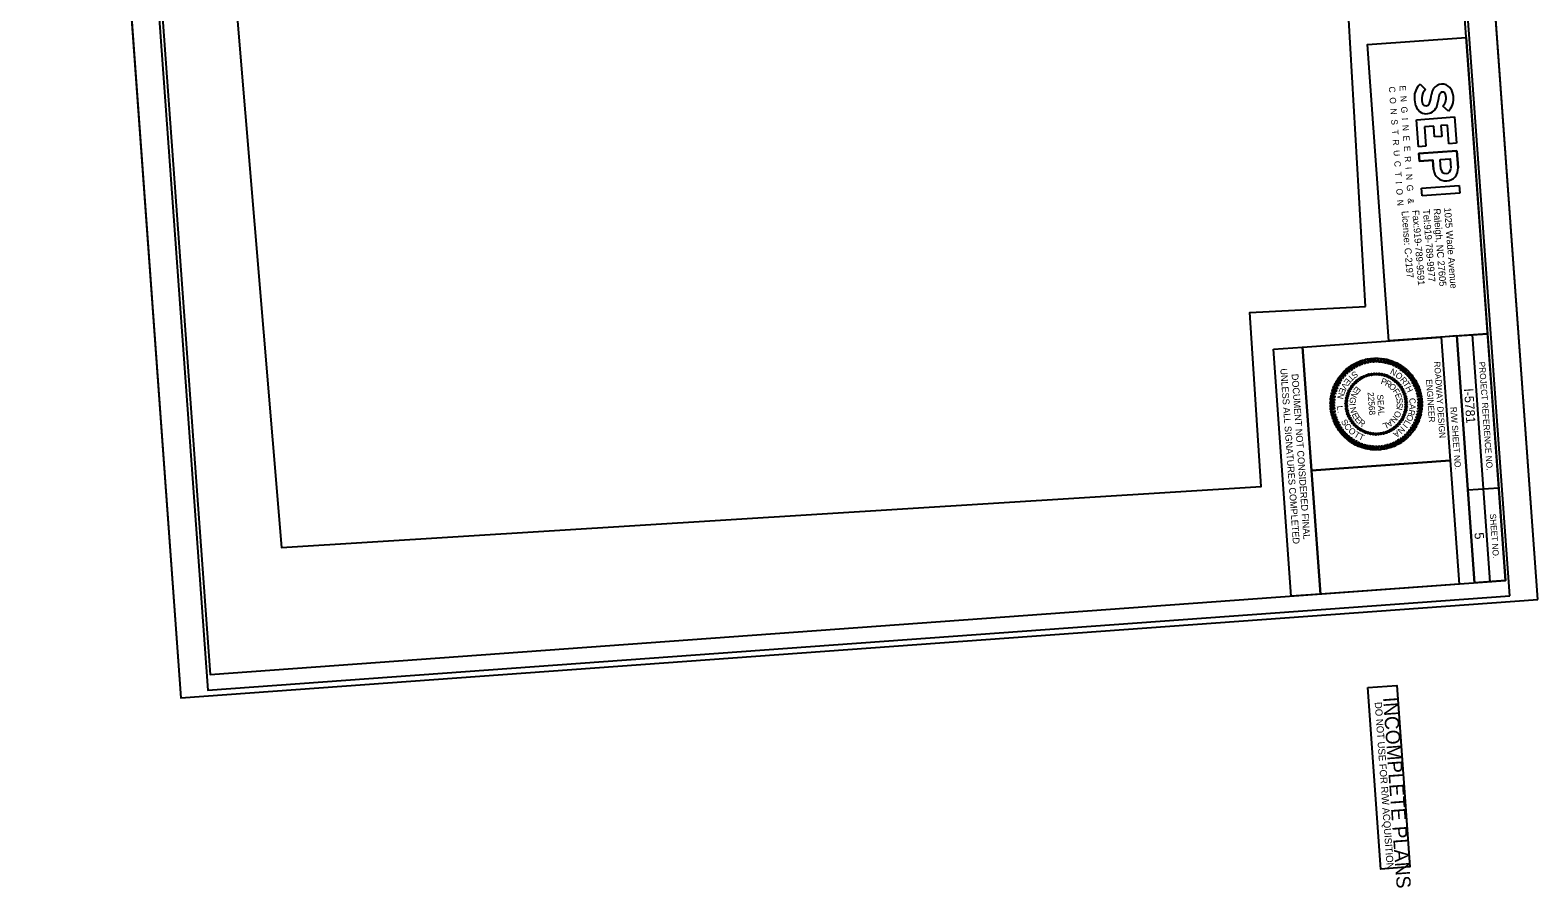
# Model space of a CAD drawing. Extents: x 2130580 to 2132747, y 641711 to 644338.
# Drawn here: x 2131528 to 2132747, y 641711 to 642404 of the extents above; entities that cross this region are included whole.
import ezdxf

# ---------------------------------------------------------------- set-up
doc = ezdxf.new("R2010")
doc.units = 0
for name, color, linetype in [('Old_Level_2', 7, 'Continuous'), ('Old_Level_58', 7, 'Continuous'), ('Old_Level_61', 7, 'Continuous'), ('Raster_Level_1', 7, 'Continuous'), ('Sheet Border Standard 30in CELL', 7, 'Continuous'), ('Sheet Cutting Line CELL', 7, 'Continuous'), ('Sheet Data Field CELL', 7, 'Continuous'), ('Sheet PE Seal Cell', 7, 'Continuous'), ('Sheet Plot Border Inside CELL', 7, 'Continuous'), ('Sheet Plot Border Outside CELL', 7, 'Continuous'), ('Sheet Sticker Exception Certification CELL', 7, 'Continuous'), ('Sheet Sticker Incomplete CELL', 7, 'Continuous')]:
    doc.layers.add(name, color=color, linetype=linetype)

msp = doc.modelspace()

# ---------------------------------------------------------------- linework, layer by layer
at = {"layer": 'Old_Level_58'}
msp.add_lwpolyline([(2132688.9, 642398), (2132706.3, 642158.6), (2132626.5, 642152.8), (2132609.1, 642392.3)], close=True, dxfattribs=at)
at = {"layer": 'Old_Level_61'}
for p, q in [((2132651.8, 642360.1), (2132656.1, 642355.9)), ((2132674.8, 642338.3), (2132670.1, 642342.4)), ((2132648.8, 642331.5), (2132679.4, 642333.7)), ((2132650.4, 642309.5), (2132648.8, 642331.5)), ((2132662.7, 642326.3), (2132655.2, 642325.8)), ((2132663.3, 642317.6), (2132662.7, 642326.3)), ((2132673.9, 642327.1), (2132668.6, 642326.8)), ((2132668.6, 642326.8), (2132669.2, 642318)), ((2132675, 642312), (2132673.9, 642327.1)), ((2132679.4, 642333.7), (2132681, 642312.4)), ((2132655.2, 642325.8), (2132656.4, 642310)), ((2132669.2, 642318), (2132663.3, 642317.6)), ((2132656.4, 642310), (2132650.4, 642309.5)), ((2132681, 642312.4), (2132675, 642312)), ((2132682.4, 642292.6), (2132681.4, 642306.4)), ((2132668.6, 642291.6), (2132668, 642299.2)), ((2132652.9, 642276.1), (2132683.4, 642278.4)), ((2132683.4, 642278.4), (2132683.9, 642272.2)), ((2132653.3, 642270), (2132652.9, 642276.1)), ((2132683.9, 642272.2), (2132653.3, 642270))]:
    msp.add_line(p, q, dxfattribs=at)
for points in [[(2132662.6, 642291.2), (2132662.1, 642298.8), (2132651.3, 642298), (2132650.8, 642304.2), (2132681.4, 642306.4)], [(2132681.4, 642306.4), (2132650.8, 642304.2), (2132651.3, 642298), (2132662.1, 642298.8), (2132662.6, 642291.2)], [(2132681.4, 642306.4), (2132682.4, 642292.6)], [(2132668, 642299.2), (2132675.9, 642299.8), (2132676.5, 642292.2)], [(2132668, 642299.2), (2132675.9, 642299.8), (2132676.5, 642292.2)], [(2132668.6, 642291.6), (2132668, 642299.2)]]:
    msp.add_lwpolyline(points, dxfattribs=at)
for centre, radius, start, end in [((2132660.5, 642349.9), 13.4, 130.5125, 183.1662), ((2132662.7, 642349), 9.54, 133.3574, 179.9159), ((2132623.6, 642356.4), 37.6, 341.9287, 353.2035), ((2132673.2, 642350.1), 12.5, 148.1705, 171.4938), ((2132669.5, 642351.7), 8.51, 41.8801, 143.8084), ((2132624.9, 642355.6), 42.5, 341.3478, 353.5291), ((2132671.9, 642350.1), 4.86, 138.9767, 170.9918), ((2132669.8, 642351.3), 2.54, 17.6741, 129.6578), ((2132663.4, 642349), 9.35, 315.7637, 19.3408), ((2132664.1, 642348.5), 14.7, 316.2757, 37.1211), ((2132667.4, 642348.9), 20.3, 179.2769, 197.9175), ((2132656.8, 642345.4), 9.06, 198.0418, 337.7347), ((2132665, 642348.6), 11.9, 177.9903, 199.1916), ((2132656.5, 642345.7), 2.95, 200.2565, 340.7914), ((2132672.5, 642291.9), 9.91, 184.1516, 4.1516), ((2132672.5, 642291.9), 9.91, 184.1516, 4.1516), ((2132672.5, 642291.9), 3.95, 184.1516, 4.1516), ((2132672.5, 642291.9), 3.95, 184.1516, 4.1516)]:
    msp.add_arc(centre, radius, start, end, dxfattribs=at)
at = {"layer": 'Raster_Level_1'}
msp.add_lwpolyline([(2132607.7, 642180.7), (2132538.9, 643362), (2131621.6, 643297.4), (2131731.3, 641985.8), (2132523.3, 642035.1), (2132514, 642175.6)], close=True, dxfattribs=at)
at = {"layer": 'Sheet Border Standard 30in CELL'}
for p, q in [((2132681.3, 642156.8), (2132668.8, 642155.9)), ((2132681.3, 642156.8), (2132695.7, 641957.3)), ((2132681.3, 642156.8), (2132695.7, 641957.3)), ((2132693.8, 642157.7), (2132708.2, 641958.2)), ((2132676.1, 642056.1), (2132563.9, 642048)), ((2132715.3, 642033.9), (2132690.3, 642032.1))]:
    msp.add_line(p, q, dxfattribs=at)
for points in [[(2132720.7, 641959.1), (2132612.4, 643455.2), (2131565.1, 643379.3), (2131673.5, 641883.2)], [(2132668.8, 642155.9), (2132676.1, 642056.1), (2132563.8, 642048), (2132556.6, 642147.8)], [(2132706.3, 642158.6), (2132720.7, 641959.1), (2132695.7, 641957.3), (2132681.3, 642156.8)], [(2132676.1, 642056.1), (2132683.3, 641956.4), (2132571.1, 641948.2), (2132563.8, 642048)]]:
    msp.add_lwpolyline(points, close=True, dxfattribs=at)
at = {"layer": 'Sheet Cutting Line CELL'}
for p, q in [((2132746.9, 641943.9), (2132625.2, 643623.5)), ((2131528.1, 643544.1), (2131649.8, 641864.5))]:
    msp.add_line(p, q, dxfattribs=at)
at = {"layer": 'Sheet PE Seal Cell'}
for points in [[(2132595.7, 642128.9), (2132593.7, 642131.3), (2132595, 642132.2), (2132596.7, 642129.6)], [(2132597.7, 642130.3), (2132595.8, 642132.8), (2132597.2, 642133.6), (2132598.6, 642130.9)], [(2132599.7, 642131.5), (2132598, 642134.1), (2132599.5, 642134.9), (2132600.7, 642132)], [(2132601.8, 642132.6), (2132600.3, 642135.3), (2132601.8, 642135.9), (2132602.9, 642133)], [(2132604, 642133.5), (2132602.7, 642136.3), (2132604.2, 642136.9), (2132605.1, 642133.9)], [(2132606.2, 642134.3), (2132605.2, 642137.2), (2132606.7, 642137.6), (2132607.3, 642134.6)], [(2132608.5, 642134.9), (2132607.6, 642137.9), (2132609.2, 642138.2), (2132609.7, 642135.1)], [(2132610.9, 642135.4), (2132610.2, 642138.4), (2132611.8, 642138.6), (2132612, 642135.5)], [(2132613.2, 642135.6), (2132612.8, 642138.7), (2132614.4, 642138.8), (2132614.4, 642135.7)], [(2132615.6, 642135.8), (2132615.3, 642138.9), (2132617, 642138.9), (2132616.7, 642135.8)], [(2132618, 642135.7), (2132617.9, 642138.9), (2132619.5, 642138.7), (2132619.1, 642135.7)], [(2132620.3, 642135.5), (2132620.5, 642138.7), (2132622.1, 642138.4), (2132621.5, 642135.4)], [(2132622.7, 642135.2), (2132623.1, 642138.3), (2132624.7, 642137.9), (2132623.8, 642134.9)], [(2132625, 642134.6), (2132625.6, 642137.7), (2132627.1, 642137.2), (2132626.1, 642134.3)], [(2132627.2, 642134), (2132628.1, 642137), (2132629.6, 642136.4), (2132628.3, 642133.6)], [(2132629.5, 642133.1), (2132630.5, 642136), (2132632, 642135.4), (2132630.5, 642132.6)], [(2132631.6, 642132.1), (2132632.9, 642135), (2132634.3, 642134.2), (2132632.6, 642131.6)], [(2132633.7, 642131), (2132635.1, 642133.7), (2132636.5, 642132.8), (2132634.7, 642130.4)], [(2132635.7, 642129.7), (2132637.3, 642132.3), (2132638.6, 642131.4), (2132636.6, 642129)], [(2132586.5, 642118.2), (2132583.7, 642119.6), (2132584.5, 642120.9), (2132587, 642119.2)], [(2132587.7, 642120.3), (2132585, 642121.8), (2132585.9, 642123.1), (2132588.3, 642121.2)], [(2132589.1, 642122.2), (2132586.5, 642123.9), (2132587.5, 642125.2), (2132589.8, 642123.1)], [(2132590.5, 642124), (2132588.1, 642125.9), (2132589.2, 642127.1), (2132591.3, 642124.9)], [(2132592.2, 642125.8), (2132589.8, 642127.9), (2132591, 642129), (2132593, 642126.6)], [(2132593.9, 642127.4), (2132591.7, 642129.6), (2132593, 642130.7), (2132594.8, 642128.1)], [(2132637.6, 642128.2), (2132639.4, 642130.8), (2132640.6, 642129.7), (2132638.5, 642127.5)], [(2132639.4, 642126.7), (2132641.4, 642129.1), (2132642.5, 642128), (2132640.2, 642125.9)], [(2132641.1, 642125), (2132643.2, 642127.3), (2132644.3, 642126.1), (2132641.8, 642124.2)], [(2132642.6, 642123.2), (2132644.9, 642125.3), (2132645.9, 642124.1), (2132643.3, 642122.3)], [(2132644, 642121.3), (2132646.5, 642123.3), (2132647.4, 642121.9), (2132644.7, 642120.4)], [(2132645.3, 642119.4), (2132647.9, 642121.1), (2132648.7, 642119.7), (2132645.9, 642118.4)], [(2132646.5, 642117.3), (2132649.2, 642118.9), (2132649.9, 642117.4), (2132647, 642116.3)], [(2132582.7, 642107), (2132579.6, 642107.3), (2132579.9, 642108.9), (2132582.8, 642108.2)], [(2132583.1, 642109.4), (2132580, 642109.9), (2132580.4, 642111.5), (2132583.4, 642110.5)], [(2132583.7, 642111.7), (2132580.7, 642112.4), (2132581.2, 642113.9), (2132584.1, 642112.8)], [(2132584.5, 642113.9), (2132581.5, 642114.9), (2132582.1, 642116.3), (2132584.9, 642115)], [(2132585.4, 642116.1), (2132582.5, 642117.2), (2132583.2, 642118.7), (2132585.9, 642117.1)], [(2132647.5, 642115.1), (2132650.3, 642116.5), (2132650.9, 642115), (2132647.9, 642114.1)], [(2132648.4, 642112.9), (2132651.2, 642114.1), (2132651.7, 642112.6), (2132648.7, 642111.8)], [(2132649.1, 642110.6), (2132652, 642111.6), (2132652.4, 642110.1), (2132649.3, 642109.5)], [(2132649.6, 642108.3), (2132652.6, 642109.1), (2132652.9, 642107.5), (2132649.8, 642107.2)], [(2132582.3, 642102.3), (2132579.1, 642102.2), (2132579.2, 642103.8), (2132582.3, 642103.5)], [(2132582.3, 642100), (2132579.2, 642099.6), (2132579.2, 642101.2), (2132582.3, 642101.1)], [(2132582.4, 642104.7), (2132579.3, 642104.8), (2132579.4, 642106.4), (2132582.5, 642105.8)], [(2132582.5, 642097.6), (2132579.4, 642097), (2132579.3, 642098.6), (2132582.4, 642098.7)], [(2132582.9, 642095.2), (2132579.9, 642094.5), (2132579.6, 642096.1), (2132582.7, 642096.4)], [(2132649.8, 642096.5), (2132652.9, 642096.2), (2132652.6, 642094.6), (2132649.6, 642095.4)], [(2132650, 642106), (2132653, 642106.6), (2132653.2, 642105), (2132650.1, 642104.9)], [(2132650.1, 642098.9), (2132653.2, 642098.8), (2132653, 642097.2), (2132650, 642097.8)], [(2132650.2, 642103.6), (2132653.3, 642104), (2132653.3, 642102.4), (2132650.2, 642102.5)], [(2132650.2, 642101.3), (2132653.3, 642101.4), (2132653.3, 642099.8), (2132650.2, 642100.1)], [(2132583.4, 642092.9), (2132580.5, 642091.9), (2132580.1, 642093.5), (2132583.1, 642094)], [(2132584.1, 642090.7), (2132581.2, 642089.5), (2132580.8, 642091), (2132583.8, 642091.8)], [(2132585, 642088.5), (2132582.2, 642087.1), (2132581.6, 642088.6), (2132584.5, 642089.5)], [(2132586, 642086.3), (2132583.3, 642084.7), (2132582.6, 642086.2), (2132585.5, 642087.3)], [(2132587.1, 642084.2), (2132584.6, 642082.5), (2132583.8, 642083.9), (2132586.6, 642085.2)], [(2132588.4, 642082.2), (2132586, 642080.3), (2132585.1, 642081.7), (2132587.8, 642083.2)], [(2132644.8, 642083.3), (2132647.5, 642081.8), (2132646.6, 642080.5), (2132644.2, 642082.4)], [(2132646, 642085.4), (2132648.8, 642084), (2132648, 642082.6), (2132645.4, 642084.4)], [(2132647.1, 642087.5), (2132650, 642086.3), (2132649.2, 642084.9), (2132646.6, 642086.5)], [(2132648, 642089.7), (2132651, 642088.7), (2132650.3, 642087.2), (2132647.6, 642088.6)], [(2132648.8, 642091.9), (2132651.8, 642091.2), (2132651.3, 642089.7), (2132648.4, 642090.8)], [(2132649.4, 642094.2), (2132652.5, 642093.7), (2132652, 642092.1), (2132649.1, 642093.1)], [(2132589.9, 642080.4), (2132587.6, 642078.2), (2132586.6, 642079.5), (2132589.2, 642081.2)], [(2132591.4, 642078.6), (2132589.3, 642076.3), (2132588.2, 642077.5), (2132590.7, 642079.4)], [(2132593.1, 642076.9), (2132591.1, 642074.5), (2132590, 642075.6), (2132592.3, 642077.7)], [(2132594.9, 642075.3), (2132593.1, 642072.8), (2132591.9, 642073.9), (2132594, 642076.1)], [(2132596.8, 642073.9), (2132595.2, 642071.3), (2132593.9, 642072.2), (2132595.9, 642074.6)], [(2132598.8, 642072.6), (2132597.3, 642069.9), (2132596, 642070.7), (2132597.8, 642073.2)], [(2132600.9, 642071.5), (2132599.6, 642068.6), (2132598.2, 642069.4), (2132599.9, 642072)], [(2132603, 642070.5), (2132602, 642067.5), (2132600.5, 642068.2), (2132602, 642070.9)], [(2132628.5, 642070.1), (2132629.8, 642067.2), (2132628.2, 642066.7), (2132627.4, 642069.7)], [(2132630.7, 642071), (2132632.2, 642068.3), (2132630.7, 642067.6), (2132629.6, 642070.5)], [(2132632.8, 642072.1), (2132634.5, 642069.5), (2132633, 642068.7), (2132631.8, 642071.5)], [(2132634.8, 642073.3), (2132636.7, 642070.8), (2132635.3, 642070), (2132633.8, 642072.7)], [(2132636.7, 642074.7), (2132638.8, 642072.3), (2132637.5, 642071.4), (2132635.8, 642074)], [(2132638.6, 642076.2), (2132640.8, 642074), (2132639.5, 642072.9), (2132637.7, 642075.4)], [(2132640.3, 642077.8), (2132642.7, 642075.7), (2132641.5, 642074.6), (2132639.5, 642077)], [(2132641.9, 642079.5), (2132644.4, 642077.6), (2132643.3, 642076.5), (2132641.2, 642078.7)], [(2132643.4, 642081.4), (2132646, 642079.7), (2132645, 642078.4), (2132642.7, 642080.5)], [(2132605.2, 642069.6), (2132604.4, 642066.6), (2132602.9, 642067.2), (2132604.2, 642070)], [(2132607.5, 642068.9), (2132606.9, 642065.9), (2132605.3, 642066.4), (2132606.4, 642069.2)], [(2132609.8, 642068.4), (2132609.4, 642065.3), (2132607.8, 642065.7), (2132608.7, 642068.6)], [(2132612.2, 642068), (2132612, 642064.9), (2132610.4, 642065.2), (2132611, 642068.2)], [(2132614.5, 642067.8), (2132614.6, 642064.7), (2132612.9, 642064.9), (2132613.4, 642067.9)], [(2132616.9, 642067.8), (2132617.1, 642064.7), (2132615.5, 642064.7), (2132615.8, 642067.8)], [(2132619.3, 642067.9), (2132619.7, 642064.8), (2132618.1, 642064.8), (2132618.1, 642067.8)], [(2132621.6, 642068.2), (2132622.3, 642065.2), (2132620.7, 642065), (2132620.5, 642068.1)], [(2132623.9, 642068.7), (2132624.8, 642065.7), (2132623.2, 642065.4), (2132622.8, 642068.4)], [(2132626.2, 642069.3), (2132627.3, 642066.4), (2132625.8, 642066), (2132625.1, 642069)]]:
    msp.add_lwpolyline(points, close=True, dxfattribs=at)
for centre in [(2132599.4, 642119.2), (2132600.9, 642120.6), (2132602.6, 642121.9), (2132604.4, 642123), (2132606.3, 642123.9), (2132608.3, 642124.7), (2132610.3, 642125.3), (2132612.4, 642125.7), (2132614.5, 642126), (2132616.6, 642126), (2132618.7, 642125.9), (2132620.8, 642125.6), (2132622.9, 642125.1), (2132624.9, 642124.5), (2132626.8, 642123.6), (2132628.7, 642122.6), (2132630.4, 642121.4), (2132632.1, 642120.1), (2132633.6, 642118.7), (2132592.4, 642106.4), (2132592.9, 642108.4), (2132593.6, 642110.4), (2132594.4, 642112.4), (2132595.4, 642114.2), (2132596.6, 642116), (2132597.9, 642117.7), (2132635, 642117.1), (2132636.3, 642115.4), (2132637.4, 642113.6), (2132638.4, 642111.7), (2132639.2, 642109.7), (2132639.8, 642107.7), (2132592, 642102.2), (2132592.1, 642100), (2132592.1, 642104.3), (2132592.3, 642097.9), (2132592.7, 642095.9), (2132593.3, 642093.8), (2132639.6, 642095.2), (2132640.1, 642097.2), (2132640.2, 642105.6), (2132640.4, 642099.3), (2132640.4, 642103.5), (2132640.5, 642101.4), (2132594.1, 642091.9), (2132595.1, 642090), (2132596.2, 642088.2), (2132597.4, 642086.5), (2132598.8, 642084.9), (2132600.4, 642083.5), (2132602, 642082.1), (2132629.9, 642081.7), (2132631.5, 642083), (2132633.1, 642084.4), (2132634.6, 642085.9), (2132635.9, 642087.6), (2132637.1, 642089.4), (2132638.1, 642091.2), (2132638.9, 642093.2), (2132603.8, 642081), (2132605.7, 642080), (2132607.6, 642079.1), (2132609.6, 642078.5), (2132611.7, 642078), (2132613.8, 642077.7), (2132615.9, 642077.5), (2132618, 642077.6), (2132620.1, 642077.9), (2132622.2, 642078.3), (2132624.2, 642078.9), (2132626.2, 642079.7), (2132628.1, 642080.6)]:
    msp.add_circle(centre, 0.75, dxfattribs=at)
at = {"layer": 'Sheet Plot Border Inside CELL'}
msp.add_lwpolyline([(2132724.2, 641946.8), (2132603.8, 643608.9), (2131551.4, 643532.7), (2131671.8, 641870.6)], close=True, dxfattribs=at)
at = {"layer": 'Sheet Plot Border Outside CELL'}
msp.add_lwpolyline([(2132746.9, 641943.9), (2132625.2, 643623.5), (2131528.1, 643544.1), (2131649.8, 641864.5)], close=True, dxfattribs=at)
at = {"layer": 'Sheet Sticker Exception Certification CELL'}
for p, q in [((2132533.2, 642146.1), (2132556.6, 642147.8)), ((2132547.6, 641946.6), (2132533.2, 642146.1)), ((2132556.6, 642147.8), (2132571.1, 641948.3)), ((2132571.1, 641948.3), (2132547.6, 641946.6))]:
    msp.add_line(p, q, dxfattribs=at)
at = {"layer": 'Sheet Sticker Incomplete CELL'}
msp.add_lwpolyline([(2132609.4, 641872.8), (2132632.8, 641874.5), (2132643.4, 641727.8), (2132620, 641726.1)], close=True, dxfattribs=at)

# ---------------------------------------------------------------- texts
at = {"layer": 'Old_Level_2'}
for s, height, rotation, p in [('C  O  N  S  T  R  U  C  T  I  O  N', 5.1, 274.1516, (2132626.4, 642358.1)), ('E  N  G  I  N  E  E  R  I  N  G   &', 5.1, 274.1516, (2132635, 642358.9)), ('License: C-2197', 5.589, 274.491, (2132636.7, 642257.6)), ('Fax:919-789-9591', 5.589, 274.491, (2132645.3, 642258.3)), ('Tel:919-789-9977 ', 5.589, 274.491, (2132653.9, 642259)), ('Raleigh, NC 27605', 5.589, 274.491, (2132662.5, 642259.6)), ('1025 Wade Avenue', 5.589, 274.491, (2132671.1, 642260.3))]:
    msp.add_text(s, height=height, rotation=rotation, dxfattribs=at).set_placement(p)
at = {"layer": 'Sheet Border Standard 30in CELL'}
for s, p in [('ROADWAY DESIGN', (2132662.9, 642136)), ('PROJECT REFERENCE NO.', (2132699.2, 642135.8)), ('ENGINEER', (2132656.4, 642121.6)), ('R/W SHEET NO.', (2132676.2, 642099.3)), ('SHEET NO.', (2132708, 642013))]:
    msp.add_text(s, height=5, rotation=274.143, dxfattribs=at).set_placement(p)
at = {"layer": 'Sheet Data Field CELL'}
for s, p in [('I-5781   ', (2132687.1, 642114.2)), ('5', (2132695.6, 641997.8))]:
    msp.add_text(s, height=7.5, rotation=274.143, dxfattribs=at).set_placement(p)
at = {"layer": 'Sheet PE Seal Cell'}
for s, rotation, p in [('E', 232.2169, (2132592.4, 642123.1)), ('T', 224.4277, (2132595.5, 642126.1)), ('S', 216.3144, (2132599.2, 642128.8)), ('P', 342.4774, (2132619.6, 642118.2)), ('R', 330.7152, (2132622.8, 642117.1)), ('N', 332.6775, (2132627, 642126.5)), ('O', 322.4671, (2132631.2, 642124.2)), ('R', 311.742, (2132635.1, 642121)), ('T', 303.5333, (2132637.7, 642118.1)), ('N', 256.8619, (2132585.7, 642111.2)), ('E', 248.8821, (2132587.3, 642115.4)), ('V', 240.1968, (2132589.7, 642119.6)), ('G', 258.8059, (2132595.4, 642107.7)), ('N', 243.7559, (2132597.6, 642112.9)), ('E', 231.9936, (2132600.3, 642116.5)), ('22568', 274.143, (2132609.3, 642111.2)), ('SEAL', 274.143, (2132616.9, 642109.3)), ('O', 318.6157, (2132625.9, 642115.4)), ('F', 302.8069, (2132629.3, 642112.3)), ('E', 291.129, (2132631.1, 642109.4)), ('H', 295.7441, (2132639.7, 642115)), ('L', 276.9587, (2132584.3, 642100.2)), ('.', 284.4238, (2132584.8, 642096)), ('I', 273.856, (2132594.5, 642102.1)), ('N', 282.6114, (2132594.8, 642098.8)), ('E', 297.6615, (2132596.3, 642093.3)), ('O', 246.6934, (2132632.2, 642096.8)), ('S', 279.3667, (2132632.4, 642106.2)), ('I', 255.4488, (2132632.8, 642099.3)), ('S', 267.4078, (2132632.9, 642102.8)), ('R', 257.5523, (2132642.9, 642097.7)), ('C', 276.1049, (2132642.8, 642106.4)), ('A', 266.5998, (2132643.2, 642101.9)), ('S', 300.3931, (2132587.6, 642087.6)), ('C', 308.5065, (2132589.9, 642083.7)), ('O', 318.0115, (2132593.2, 642079.6)), ('E', 309.4237, (2132598.4, 642089.4)), ('R', 321.186, (2132601.3, 642086)), ('L', 202.4987, (2132624.2, 642087.1)), ('A', 215.8346, (2132627.4, 642089.3)), ('N', 230.8846, (2132630.2, 642092.7)), ('N', 225.2134, (2132636.5, 642084.1)), ('I', 231.1534, (2132638.3, 642086.3)), ('L', 238.6185, (2132640.1, 642089.3)), ('O', 249.3437, (2132642, 642093.9)), ('T', 328.7367, (2132597.8, 642075.7)), ('T', 336.5259, (2132601.5, 642073.5)), ('A', 215.003, (2132633.1, 642080.8))]:
    msp.add_text(s, height=5, rotation=rotation, dxfattribs=at).set_placement(p)
at = {"layer": 'Sheet Sticker Exception Certification CELL'}
for s, p in [('UNLESS ALL SIGNATURES COMPLETED', (2132538.7, 642130.4)), ('DOCUMENT NOT CONSIDERED FINAL', (2132547.8, 642126))]:
    msp.add_text(s, height=5.5, rotation=274.143, dxfattribs=at).set_placement(p)
at = {"layer": 'Sheet Sticker Incomplete CELL'}
for s, height, p in [('INCOMPLETE PLANS', 11.52, (2132621.7, 641864.7)), ('DO NOT USE FOR R/W ACQUISITION', 5.76, (2132615, 641860.9))]:
    msp.add_text(s, height=height, rotation=274.143, dxfattribs=at).set_placement(p)

doc.saveas('drawing.dxf')
